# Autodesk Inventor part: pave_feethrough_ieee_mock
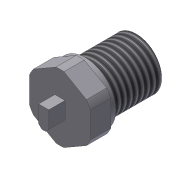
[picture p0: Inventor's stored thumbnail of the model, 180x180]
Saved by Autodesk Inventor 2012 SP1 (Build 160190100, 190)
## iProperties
Created: 2012-03
Part Number: pave_feethrough_ieee_mock
Material: Aluminum-6061
Document SubType Name: Modeling
Designer: jdh
Density: 2.71 g/cm^3
Mass: 122.917 g
Surface Area: 80.1716 cm^2
Volume: 45.3569 cm^3
Author: jdh
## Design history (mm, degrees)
sketch "Sketch1"
  geometry: L1 (2.509, 20.548)-(16.541, 12.447); L2 (19.05, 8.101)-(19.05, -8.101); L3 (16.541, -12.447)-(2.509, -20.548); L4 (-2.509, -20.548)-(-16.541, -12.447); L5 (-19.05, -8.101)-(-19.05, 8.101); L6 (-16.541, 12.447)-(-2.509, 20.548); A1 r 20.701 centre (0, 0) between (2.509, 20.548) and (-2.509, 20.548); A2 r 20.701 centre (0, 0) between (19.05, 8.101) and (16.541, 12.447); A3 r 20.701 centre (0, 0) between (16.541, -12.447) and (19.05, -8.101); A4 r 20.701 centre (0, 0) between (-2.509, -20.548) and (2.509, -20.548); A5 r 20.701 centre (0, 0) between (-16.541, 12.447) and (-19.05, 8.101); A6 r 20.701 centre (0, 0) between (-19.05, -8.101) and (-16.541, -12.447); 2 further points
  constraints: 12 end point, 12 point on circle, 6 centre point, 2 coincident, 7 other
  dimensions: "d1" = 38.1 distance between parallel lines of L5 L2
extrude "Extrusion1" new body sketch "Sketch1" distance "d2" = 12.7; taper "d3" = 0 deg
sketch "Sketch2"
  geometry: C1 r 18.923 at (0, 0); A1 r 20.701 centre (0, 0) between (19.05, 8.101) and (16.541, 12.447) reference
  constraints: 1 centre point, 1 coincident
  dimensions: "d6" = 37.846 diameter of C1
extrude "Extrusion2" join sketch "Sketch2" distance "d4" = 3.302; taper "d5" = 0 deg
sketch "Sketch3"
  geometry: C1 r 18.923 at (0, 0) reference; C2 r 15.875 at (0, 0)
  constraints: 1 centre point, 1 coincident
  dimensions: "d7" = 31.75 diameter of C2
extrude "Extrusion3" join sketch "Sketch3" distance "d8" = 31.75; taper "d9" = 0 deg
thread "Thread1" dims "d10" = 25.4, "d11" = 0
sketch "Sketch4"
  geometry: L1 (-3.175, 5.334)-(3.175, 5.334); L2 (3.175, 5.334)-(3.175, -5.334); L3 (3.175, -5.334)-(-3.175, -5.334); L4 (-3.175, -5.334)-(-3.175, 5.334); L5 (-3.175, -5.334)-(-1.143, -7.366); L6 (-3.175, -5.334)-(-0.301, -5.334); L7 (3.175, -5.334)-(1.143, -7.366); L8 (3.175, -5.334)-(12.473, -5.334); L9 (-1.143, -7.366)-(1.143, -7.366); L10 (0, 5.334)-(0, -5.334); A1 r 20.701 centre (0, 0) between (19.05, 8.101) and (16.541, 12.447) reference; 1 further point
  constraints: 20 end point, 3 horizontal, 3 midpoint, 3 parallel, 1 coincident, 1 equal length, 1 perpendicular
  dimensions: "d12" = 45 deg angle of L5 L6; "d13" = 135 deg angle of L7 L8; "d14" = 6.35 distance of L1.start L1.end; "d15" = 2.032 distance between parallel lines of L9 L3; "d17" = 12.7 distance between parallel lines of L9 L1
extrude "Extrusion4" join sketch "Sketch4" distance "d18" = 10.16; taper "d19" = 0 deg
body "Solid1"
other parameters: "d0" = 41.402
